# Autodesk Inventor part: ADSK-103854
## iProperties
Shininess: 25.0
Created: 2001-04
Part Number: ADSK-103854
Document SubType Name: Modeling
Designer: Administrator
Stock Number: ADSK-103854
Density: 1 g/cm^3
Density: 0.0
Volumn: 0.0
Area: 0.0
PropertySet Name: Model Information
Control State: 0
Master: False
Checked Out: False
Author: Administrator
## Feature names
1. Extrusion1
